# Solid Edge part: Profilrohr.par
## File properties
Username: bmolnar
Dokumentum tartalom típus: 0
Author: bmolnar
Last saved by: bmolnar
Revision: 78
Sűrűség: 0,000 kg/m^3
Pontosság: 0,990
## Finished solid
Body 1: solid body, 115 faces, 338 edges, 224 vertices.
  Faces by surface: cylinder 59, plane 56
  Edges by curve: line 220, circle 118
Bounding box of the edges (mm): 95.500 x 95.500 x 39.000, from (-47.75, -47.75, -10) to (47.75, 47.75, 29).
Cylindrical faces by radius (mm): R0.2 x24, R0.5 x24, R1 x4, R10 x4, R13.5 x2, R40 x1
Planar faces by outward normal: +x 13, +y 14, +z 1, -x 13, -y 14, -z 1
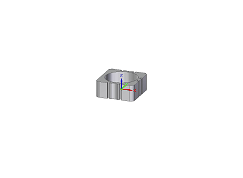
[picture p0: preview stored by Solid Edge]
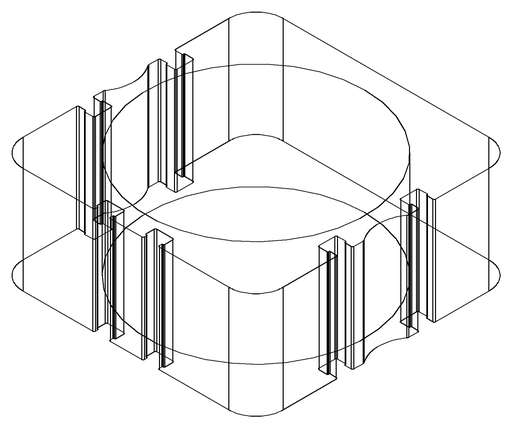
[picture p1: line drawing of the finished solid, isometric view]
